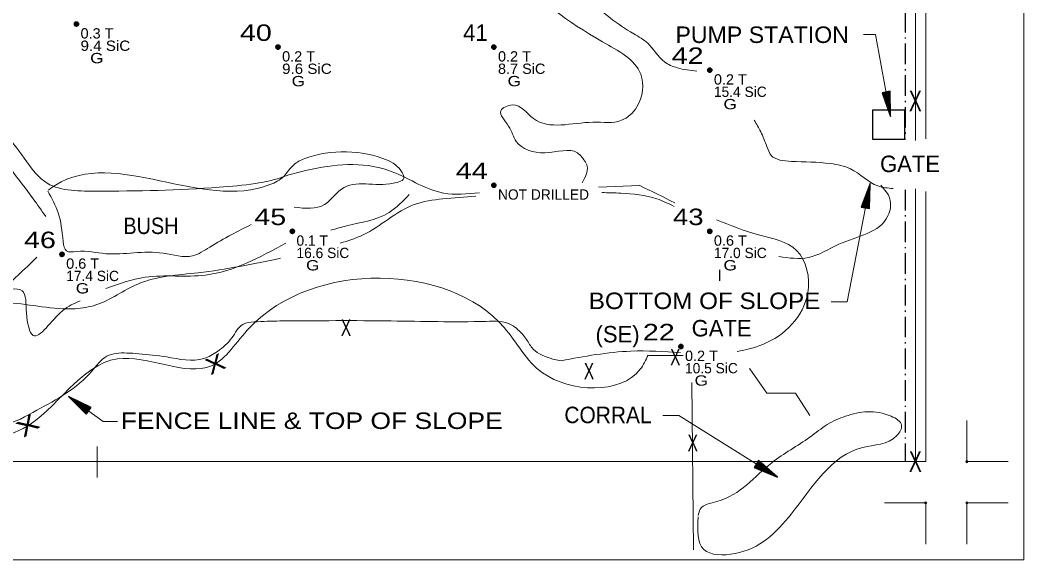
# Model space of a CAD drawing. Extents: x -496 to 480, y -450 to 700.
# Drawn here: x -37.5 to 450, y -450 to -188 of the extents above; entities that cross this region are included whole.
import ezdxf
from ezdxf.enums import TextEntityAlignment as Align

# ---------------------------------------------------------------- set-up
doc = ezdxf.new("R2010")
doc.units = 0
doc.header["$LTSCALE"] = 2
doc.header["$PDMODE"] = 32
doc.header["$PDSIZE"] = 1
doc.linetypes.add('DOT_DASHED', pattern=[7.7, 5, -1.2, 0.3, -1.2])
doc.linetypes.add('LONG_DASHED', pattern=[7.5, 6, -1.5])
for name, color, linetype, lineweight in [('1', 7, 'Continuous', 13), ('2', 7, 'Continuous', 35), ('3', 7, 'Continuous', 13), ('4', 7, 'Continuous', 25)]:
    doc.layers.add(name, color=color, linetype=linetype, lineweight=lineweight)

msp = doc.modelspace()

# ---------------------------------------------------------------- linework, layer by layer
at = {"layer": '1'}
for p, q in [((402.281, -245.555), (402.281, 402.339)), ((402.281, -402.333), (402.281, -271.26)), ((422.281, -402.333), (422.281, -382.333)), ((-0.017, -395.027), (-0.017, -410.027)), ((-311.567, -402.333), (402.281, -402.333)), ((422.281, -402.333), (442.281, -402.333)), ((402.281, -422.333), (382.281, -422.333)), ((402.281, -422.333), (402.281, -442.333)), ((422.281, -422.333), (422.281, -442.333)), ((422.281, -422.333), (442.281, -422.333)), ((-450.017, -450.027), (449.983, -450.027))]:
    msp.add_line(p, q, dxfattribs=at)
msp.add_lwpolyline([(449.983, -450.027), (449.983, 399.973), (449.983, 699.973), (-450.017, 699.973), (-450.017, 49.973), (-450.017, -450.027)], dxfattribs=at)
for p in [(422.281, -402.333), (402.281, -422.333), (422.281, -422.333)]:
    msp.add_point(p, dxfattribs=at)
at = {"layer": '2', "linetype": 'LONG_DASHED', "lineweight": 25}
msp.add_line((302.281, -314.553), (302.281, -309.148), dxfattribs=at)
at = {"layer": '2'}
for centre in [(-10.129, -189.936), (87.731, -201.111), (192.581, -201.111), (297.431, -212.286), (192.581, -268.161), (94.721, -290.511), (297.431, -290.511), (-17.119, -301.686), (283.395, -346.451)]:
    msp.add_circle(centre, 1, dxfattribs=at)
for points in [[(-10.14, -189.049), (-9.409, -189.453), (-9.258, -190.302), (-9.943, -190.83), (-10.752, -190.599), (-11.038, -189.841), (-10.791, -189.279), (-10.218, -189.111), (-9.544, -189.605), (-9.561, -190.347), (-10.078, -190.605), (-10.6, -190.436), (-10.825, -189.79), (-10.241, -189.324), (-9.803, -189.858), (-9.842, -190.341), (-10.471, -190.206), (-10.325, -189.571), (-10.033, -190.122)], [(87.72, -200.224), (88.451, -200.628), (88.602, -201.477), (87.917, -202.005), (87.108, -201.774), (86.822, -201.016), (87.069, -200.454), (87.642, -200.286), (88.316, -200.78), (88.299, -201.522), (87.782, -201.78), (87.26, -201.611), (87.035, -200.965), (87.619, -200.499), (88.057, -201.033), (88.018, -201.516), (87.389, -201.381), (87.535, -200.746), (87.827, -201.297)], [(192.57, -200.224), (193.301, -200.628), (193.452, -201.477), (192.767, -202.005), (191.958, -201.774), (191.672, -201.016), (191.919, -200.454), (192.492, -200.286), (193.166, -200.78), (193.149, -201.522), (192.632, -201.78), (192.11, -201.611), (191.885, -200.965), (192.469, -200.499), (192.907, -201.033), (192.868, -201.516), (192.239, -201.381), (192.385, -200.746), (192.677, -201.297)], [(297.42, -211.399), (298.151, -211.803), (298.302, -212.652), (297.617, -213.18), (296.808, -212.949), (296.522, -212.191), (296.769, -211.629), (297.342, -211.461), (298.016, -211.955), (297.999, -212.697), (297.482, -212.955), (296.96, -212.786), (296.735, -212.14), (297.319, -211.674), (297.757, -212.208), (297.718, -212.691), (297.089, -212.556), (297.235, -211.921), (297.527, -212.472)], [(192.57, -267.274), (193.301, -267.678), (193.452, -268.527), (192.767, -269.055), (191.958, -268.824), (191.672, -268.066), (191.919, -267.504), (192.492, -267.336), (193.166, -267.83), (193.149, -268.572), (192.632, -268.83), (192.11, -268.661), (191.885, -268.015), (192.469, -267.549), (192.907, -268.083), (192.868, -268.566), (192.239, -268.431), (192.385, -267.796), (192.677, -268.347)], [(94.71, -289.624), (95.441, -290.028), (95.592, -290.877), (94.907, -291.405), (94.098, -291.174), (93.812, -290.416), (94.059, -289.854), (94.632, -289.686), (95.306, -290.18), (95.289, -290.922), (94.772, -291.18), (94.25, -291.011), (94.025, -290.365), (94.609, -289.899), (95.047, -290.433), (95.008, -290.916), (94.379, -290.781), (94.525, -290.146), (94.817, -290.697)], [(297.42, -289.624), (298.151, -290.028), (298.302, -290.877), (297.617, -291.405), (296.808, -291.174), (296.522, -290.416), (296.769, -289.854), (297.342, -289.686), (298.016, -290.18), (297.999, -290.922), (297.482, -291.18), (296.96, -291.011), (296.735, -290.365), (297.319, -289.899), (297.757, -290.433), (297.718, -290.916), (297.089, -290.781), (297.235, -290.146), (297.527, -290.697)], [(-17.13, -300.799), (-16.399, -301.203), (-16.248, -302.052), (-16.933, -302.58), (-17.742, -302.349), (-18.028, -301.591), (-17.781, -301.029), (-17.208, -300.861), (-16.534, -301.355), (-16.551, -302.097), (-17.068, -302.355), (-17.59, -302.186), (-17.815, -301.54), (-17.231, -301.074), (-16.793, -301.608), (-16.832, -302.091), (-17.461, -301.956), (-17.315, -301.321), (-17.023, -301.872)], [(283.384, -345.564), (284.114, -345.968), (284.266, -346.817), (283.581, -347.345), (282.772, -347.114), (282.485, -346.356), (282.732, -345.794), (283.305, -345.626), (283.979, -346.12), (283.963, -346.862), (283.446, -347.12), (282.923, -346.951), (282.699, -346.305), (283.283, -345.839), (283.721, -346.373), (283.682, -346.856), (283.053, -346.721), (283.199, -346.086), (283.491, -346.637)]]:
    msp.add_spline(points, degree=3, dxfattribs=at)
at = {"layer": '3'}
for p, q in [((397.281, -246.457), (397.281, 397.339)), ((243.463, -269.11), (263.483, -268.334)), ((397.281, -402.333), (397.281, -269.907)), ((267.785, -350.812), (284.472, -350.812)), ((221.211, -352.551), (225.272, -353.321)), ((316.635, -357.231), (316.864, -357.245)), ((288.691, -363.868), (289.578, -445.177))]:
    msp.add_line(p, q, dxfattribs=at)
at = {"layer": '3', "linetype": 'DOT_DASHED', "lineweight": 25}
for p, q in [((392.281, 385.802), (392.281, -246.006)), ((392.281, -270.358), (392.281, -402.333))]:
    msp.add_line(p, q, dxfattribs=at)
at = {"layer": '3', "lineweight": 25}
msp.add_lwpolyline([(391.96, -246.006), (376.61, -246.006), (376.61, -231.575), (391.96, -231.575)], close=True, dxfattribs=at)
at = {"layer": '3'}
msp.add_lwpolyline([(316.864, -357.245), (325.101, -369.072), (339.001, -369.072), (345.951, -379.87)], dxfattribs=at)
for points in [[(237.229, -257.097), (233.19, -252.437), (217.369, -252.437), (203.408, -246.859), (199.685, -239.422), (195.963, -231.985), (201.547, -229.197), (211.784, -235.704), (240.636, -237.563), (254.596, -236.633), (262.042, -230.126), (263.903, -214.323), (245.289, -198.519), (200.616, -166.912), (152.22, -131.587), (114.062, -106.488), (92.656, -93.473), (61.943, -81.388), (39.607, -72.092), (6.102, -57.218)], [(38.939, -56.557), (49.996, -65.901), (63.179, -73.122), (73.81, -79.069), (97.624, -85.865), (114.634, -94.36), (131.219, -110.076), (146.103, -121.97), (167.791, -138.96), (185.226, -151.703), (201.386, -158.499), (225.625, -167.844), (249.014, -186.958), (260.496, -194.604), (267.3, -199.276), (275.38, -208.196), (281.758, -211.169), (291.16, -212.829)], [(-25.045, -283.284), (-31.126, -274.748), (-52.532, -246.859), (-60.908, -236.633), (-66.492, -226.408), (-62.769, -222.689), (-51.601, -232.915), (-36.71, -253.366), (-25.542, -266.381), (-1.344, -271.029), (59.151, -269.17), (76.834, -267.311), (88.933, -264.522), (91.725, -263.592), (101.963, -260.803), (141.052, -260.803), (168.042, -271.959), (185.632, -271.816)], [(319.047, -236.557), (322.157, -242.177), (325.134, -249.398), (327.26, -253.645), (337.041, -256.619)], [(-23.812, -270.542), (-20.322, -268.129), (83.83, -267.861), (90.541, -263.839), (95.373, -258.208), (100.742, -255.259), (140.47, -255.795), (144.765, -258.208), (148.523, -265.448), (145.571, -266.788), (131.88, -267.593), (119.801, -269.201), (110.406, -277.513), (95.577, -278.829)], [(235.413, -267.004), (237.844, -258.944), (237.441, -257.607)], [(337.041, -256.619), (356.083, -257.668), (365.709, -260.149), (379.06, -268.523), (386.512, -269.764)], [(74.768, -287.153), (65.04, -292.26), (54.571, -298.159), (46.249, -302.449), (32.022, -301.108), (4.105, -301.376), (-10.122, -300.304), (-14.954, -300.036), (-16.564, -295.478), (-18.98, -281.535), (-24.081, -271.078)], [(113.458, -289.966), (121.08, -287.878), (141.734, -281.363), (151.491, -272.687)], [(280.066, -278.406), (271.705, -274.777), (254.223, -272.019), (244.978, -271.733)], [(263.3, -268.247), (263.483, -268.334), (280.403, -276.725)], [(380.489, -268.161), (384.875, -274.777), (383.955, -283.048), (360.033, -296.833), (345.311, -303.266), (331.019, -302.783)], [(183.749, -273.429), (167.735, -274.777), (153.934, -277.534), (129.091, -292.238), (117.955, -296.293)], [(300.692, -284.977), (321.096, -292.221), (339.575, -299.821), (345.011, -320.451), (323.27, -345.424), (310.731, -348.927)], [(4.106, -318.322), (23.247, -312.851), (52.597, -311.765), (91.527, -296.198)], [(-298.323, -391.257), (-287.066, -396.527), (-274.036, -416.049), (-254.492, -416.978), (-237.739, -413.26), (-205.165, -398.386), (-196.789, -397.457), (-182.828, -397.457), (-178.175, -390.02), (-167.007, -380.723), (-87.898, -351.905), (-56.254, -327.736), (-38.571, -311.932), (-29.348, -303.089)], [(-155.247, -423.81), (-112.142, -391.328), (-35.973, -386.256), (9.729, -352.442), (55.43, -355.824), (74.049, -337.226), (197.613, -337.226), (216.232, -359.205), (263.626, -357.515), (267.5, -350.576)], [(88.896, -303.619), (49.044, -310.618), (19.602, -316.132), (-0.64, -326.242), (-10.761, -328.08), (-42.964, -325.323), (-52.165, -325.323)], [(-303.447, -400.25), (-285.473, -407.314), (-269.167, -417.086), (-250.688, -411.657), (-240.904, -404.057), (-222.425, -400.799), (-211.554, -404.057), (-202.858, -411.657), (-194.162, -407.314), (-186.552, -394.284), (-144.158, -367.14), (-64.804, -328.052), (-48.498, -320.451), (-36.541, -319.365), (-34.367, -330.223), (-31.106, -341.081), (-16.974, -329.138), (-8.336, -324.238)], [(88.718, -334.024), (76.16, -334.535), (70.748, -335.693), (65.336, -342.257), (58.378, -348.821), (51.807, -352.296), (33.638, -351.524), (20.109, -349.98), (14.31, -349.593), (4.646, -351.138), (-2.698, -358.474), (-29.371, -377.394), (-45.607, -384.73), (-71.12, -385.116), (-102.045, -386.66), (-115.443, -388.108)], [(221.211, -352.551), (211.631, -347.665), (208.37, -342.982), (204.293, -338.299), (201.032, -335.856), (188.802, -334.227), (142.735, -334.024), (88.718, -334.024)], [(283.213, -349.344), (259.134, -348.682), (225.272, -353.321)], [(291.812, -428.43), (292.823, -425.4), (300.913, -421.697), (327.542, -402.842), (346.081, -390.385), (354.508, -384.324), (363.272, -380.284), (385.519, -380.284), (390.575, -384.661), (388.216, -389.711), (371.699, -395.435), (336.98, -427.757), (309.677, -446.948), (294.508, -444.928), (291.812, -429.104)]]:
    msp.add_spline(points, degree=3, dxfattribs=at)
at = {"layer": '4', "lineweight": 13}
for points in [[(372.095, -195.046), (377.964, -195.046), (385.188, -234.732)], [(356.406, -324.77), (364.133, -324.77), (375.26, -267.345)], [(9.835, -382.78), (2.904, -382.78), (-13.972, -370.739)], [(274.621, -379.948), (282.374, -379.948), (330.238, -409.913)]]:
    msp.add_lwpolyline(points, dxfattribs=at)
at = {"layer": '4'}
for points in [[(385.188, -234.732), (385.007, -222.567), (381.071, -223.284)], [(375.26, -267.345), (371.014, -278.746), (374.941, -279.507)], [(-13.972, -370.739), (-5.365, -379.337), (-3.042, -376.081)], [(330.238, -409.913), (321.128, -401.85), (319.006, -405.24)]]:
    msp.add_lwpolyline(points, close=True, dxfattribs=at)
for points in [[(384.908, -222.685), (385.086, -234.167), (381.262, -223.415), (384.745, -222.759), (384.954, -233.442), (381.465, -223.575), (384.627, -222.955), (384.815, -232.677), (381.715, -223.728), (384.439, -223.121), (384.677, -231.803), (381.949, -223.928), (384.263, -223.374), (384.51, -230.755), (382.239, -224.073), (384.047, -223.633), (384.325, -229.625), (382.608, -224.29), (383.861, -223.93), (384.164, -228.378), (382.925, -224.583), (383.664, -224.296), (383.877, -226.915), (383.355, -224.9)], [(371.149, -278.672), (375.15, -267.908), (374.811, -279.315), (371.328, -278.662), (375.01, -268.632), (374.68, -279.092), (371.508, -278.522), (374.862, -269.396), (374.503, -278.86), (371.744, -278.436), (374.674, -270.26), (374.357, -278.588), (372, -278.263), (374.449, -271.297), (374.139, -278.348), (372.295, -278.101), (374.211, -272.416), (373.874, -278.011), (372.576, -277.892), (373.908, -273.637), (373.685, -277.623), (372.893, -277.623), (373.645, -275.105), (373.4, -277.171)], [(-5.376, -379.184), (-13.506, -371.073), (-3.27, -376.12), (-5.311, -379.016), (-12.906, -371.501), (-3.528, -376.146), (-5.363, -378.795), (-12.273, -371.953), (-3.813, -376.211), (-5.344, -378.544), (-11.565, -372.484), (-4.12, -376.23), (-5.395, -378.24), (-10.714, -373.119), (-4.429, -376.329), (-5.419, -377.904), (-9.795, -373.8), (-4.846, -376.43), (-5.493, -377.561), (-8.811, -374.582), (-5.277, -376.441), (-5.607, -377.161), (-7.584, -375.432), (-5.806, -376.512)], [(321.149, -402.002), (329.752, -409.607), (319.231, -405.187), (321.094, -402.173), (329.128, -409.217), (319.487, -405.146), (321.159, -402.391), (328.469, -408.804), (319.767, -405.064), (321.155, -402.643), (327.73, -408.317), (320.073, -405.026), (321.224, -402.943), (326.843, -407.734), (320.376, -404.909), (321.269, -403.277), (325.884, -407.109), (320.785, -404.783), (321.363, -403.615), (324.854, -406.388), (321.215, -404.746), (321.5, -404.007), (323.579, -405.614), (321.739, -404.643)]]:
    msp.add_lwpolyline(points, dxfattribs=at)

# ---------------------------------------------------------------- texts
at = {"layer": '2'}
for s, width, p in [(' 40', 1.3, (84.731, -198.111)), (' 42', 1.3, (294.431, -209.286)), (' 44', 1.3, (189.581, -265.161)), (' 45', 1.3, (91.721, -287.511)), (' 43', 1.25, (294.431, -287.511)), (' 46', 1.3, (-20.119, -298.686)), (' 22', 1.3, (280.394, -343.451))]:
    msp.add_text(s, height=8, dxfattribs=dict(at, width=width)).set_placement(p, align=Align.RIGHT)
for s, p in [(' 41', (189.581, -198.111)), ('(SE)', (263.347, -344.46))]:
    msp.add_text(s, height=8, dxfattribs=at).set_placement(p, align=Align.RIGHT)
for s, width, p in [('0.3 T      ', 1.05, (-8.129, -196.936)), ('9.4 SiC    ', 1.1, (-8.129, -202.936)), ('  G        ', 1.25, (-8.129, -208.936)), ('0.2 T      ', 1.05, (89.731, -208.111)), ('0.2 T      ', 1.05, (194.581, -208.111)), ('9.6 SiC    ', 1.1, (89.731, -214.111)), ('8.7 SiC    ', 1.05, (194.581, -214.111)), ('0.2 T      ', 1.05, (299.431, -219.286)), ('  G        ', 1.25, (89.731, -220.111)), ('  G        ', 1.25, (194.581, -220.111)), ('  G        ', 1.25, (299.431, -231.286)), ('0.6 T      ', 1.05, (299.431, -297.511)), ('0.6 T      ', 1.05, (-15.119, -308.686)), ('  G        ', 1.25, (96.721, -309.511)), ('  G        ', 1.25, (299.431, -309.511)), ('  G        ', 1.25, (-15.119, -320.686)), ('0.2 T      ', 1.05, (285.395, -353.451)), ('  G        ', 1.25, (285.395, -365.451))]:
    msp.add_text(s, height=5, dxfattribs=dict(at, width=width)).set_placement(p)
for s, p in [('15.4 SiC   ', (299.431, -225.286)), ('NOT DRILLED', (194.581, -275.161)), ('0.1 T      ', (96.721, -297.511)), ('16.6 SiC   ', (96.721, -303.511)), ('17.0 SiC   ', (299.431, -303.511)), ('17.4 SiC   ', (-15.119, -314.686)), ('10.5 SiC   ', (285.395, -359.451))]:
    msp.add_text(s, height=5, dxfattribs=at).set_placement(p)
at = {"layer": '3', "width": 0.7}
for height, p in [(10, (397.252, -232.321)), (8, (120.764, -341.312)), (8, (280.665, -355.602)), (8, (238.775, -362.364)), (8, (289.159, -397.254)), (10, (397.26, -407.307))]:
    msp.add_text('X', height=height, dxfattribs=at).set_placement(p, align=Align.CENTER)
at = {"layer": '3'}
for rotation, width, p in [(25.242, 1.25, (58.962, -358.531)), (33.04, 1.45, (-31.657, -388.093))]:
    msp.add_text('X', height=8, rotation=rotation, dxfattribs=dict(at, width=width)).set_placement(p, align=Align.CENTER)
at = {"layer": '4'}
for s, width, p in [('PUMP STATION', 1.05, (322.882, -199.105)), ('BUSH', 0.9, (26.043, -291.853)), ('BOTTOM OF SLOPE', 1.1, (294.893, -328.254)), ('FENCE LINE & TOP OF SLOPE', 1.2, (104.116, -386.468)), ('CORRAL', 0.95, (247.992, -383.651))]:
    msp.add_text(s, height=8, dxfattribs=dict(at, width=width)).set_placement(p, align=Align.CENTER)
for p in [(394.669, -261.79), (303.193, -341.563)]:
    msp.add_text('GATE', height=8, dxfattribs=at).set_placement(p, align=Align.CENTER)

doc.saveas('drawing.dxf')
